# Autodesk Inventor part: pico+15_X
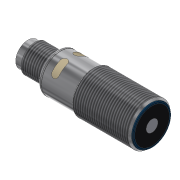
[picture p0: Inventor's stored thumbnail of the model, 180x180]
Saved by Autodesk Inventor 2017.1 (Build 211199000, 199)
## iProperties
Shininess: 20.0
Length Units: 11269
Angle Units: 11279
Time Units: 11290
Mass Units: 11283
Length Display Precision: 2
Angle Display Precision: 2
Part Number: pico+15_X
Material: Nichtrostender Stahl - 440C
Document SubType Name: Modellieren
Description: Ipc-25 /CXX/M18
Checked By: Alves
Created: 2005-08
Designer: Ohle
Manufacturer: Standard
Standards Organization: Custom
Appearance: Aluminium - poliert
Density: 0.0
Volumn: 0.0
Area: 0.0
PropertySet Name: Model Information
Control State: 0
Master: False
Checked Out: False
BESTELLNUMMER: Ipc-25 /CXX/M18
ME: ST
Title: Ipc Sensoren
Author: Ohle
Comments: keine Bemerkung
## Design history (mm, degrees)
sketch "Skizze10"
  geometry: L1 (-42.478, 0)-(2.095, 0); L2 (-38.478, 6.5)-(-38.478, 7.25); L3 (-45.9, 8)-(-45.9, 8); L4 (-22.728, 9)-(0.772, 9); L5 (2.085, 7.4)-(2.085, 2.5); L6 (2.085, 2.5)-(2.095, 2.5); L7 (2.095, 2.5)-(2.095, 0); L8 (2.095, 0)-(-82, 0); L9 (1.522, 8.25)-(1.522, 8.25); L10 (-23.478, 8.25)-(-22.728, 9); L11 (1.522, 8.25)-(0.772, 9); L12 (-49.978, 6)-(-38.978, 6); L13 (-36.878, 8.25)-(-23.478, 8.25); L14 (-50.478, 4.5)-(-42.478, 4.5); L15 (-42.478, 0)-(-42.478, 4.5); L16 (-36.978, 8.25)-(-37.478, 8.25); L17 (1.522, 8.25)-(1.522, 8.25); L18 (-38.978, 6)-(-38.478, 6.5); L19 (-50.478, 5.5)-(-50.478, 4.5); L20 (-50.478, 5.5)-(-49.978, 6); L21 (-36.978, 8.25)-(-36.978, 8.15); L22 (-36.978, 8.15)-(-36.878, 8.15); L23 (-36.878, 8.15)-(-36.878, 8.25); L24 (1.522, 8.25)-(1.595, 8.25); L25 (1.595, 8.25)-(1.795, 8.25); L26 (2.095, 7.95)-(2.095, 7.4); L27 (2.095, 7.4)-(2.085, 7.4); A1 r 1 centre (-37.478, 7.25) between (-37.478, 8.25) and (-38.478, 7.25); A2 r 0.3 centre (1.795, 7.95) between (2.095, 7.95) and (1.795, 8.25); 4 further points
  constraints: 54 end point, 8 point on line, 7 perpendicular, 5 parallel, 4 point on circle, 4 tangent, 2 centre point, 2 horizontal, 1 collinear
  dimensions: "d136" = 2.5 distance of L6.end L1.end; "d138" = 9 distance between parallel lines of L4 L8; "d171" = 4.5 distance between parallel lines of L14 L1; "d250" = 0.75 distance from line of L11.start L4; "d256" = 45 deg angle of L4 L10; "d257" = 8.25 distance between parallel lines of L8 L13; "d263" = 8.25 distance between parallel lines of L8 L16; "d266" = 12 distance from line of L2 L19.start; "d269" = 6 distance between parallel lines of L8 L12; "d289" = 135 deg angle of L11 L4; "d290" = 0.5 horizontal distance of L12.end L2.start; "d291" = 45 deg angle of L18 L12 (derived); "d293" = 0.5 horizontal distance of L19.start L12.start; "d294" = 45 deg angle of L20 L12 (derived); "d295" = 8 distance of L14.start L14.end; "d296" = 1.5 distance of L16.start point (-38.478, 8.25); "d297" = 0.1 distance of L21.end L22.end; "d298" = 8.15 distance between parallel lines of L22 L1; "d299" = 15 distance from line of L10.start L2; "d300" = 1 radius of A1; "d331" = 0.01 distance between parallel lines of L5 L7; "d334" = 0.5 distance of L24.end point (2.095, 8.25); "d335" = 0.3 radius of A2; "d337" = 25 distance of L10.start L11.start; "d338" = 0.01 distance between parallel lines of L26 L5; "d339" = 7.4 distance between parallel lines of L8 L27
revolve "Grundkörper pico+" sketch "Skizze10" stored, may be unused: angle "d168" = 90 deg
feature "Gewinde M12" dims "d174" = 10, "d175" = 0
feature "Gewinde M 18" dims "d179" = 10, "d180" = 0
workplane "Arbeitsebene1"
workplane "Arbeitsebene2"
sketch "Skizze13"
  geometry: L1 (-3.409, -3.409)-(3.61, 3.61); L2 (-3.439, 3.439)-(4.105, -4.105); L3 (-12.6, 0)-(12.6, 0) reference; C1 r 0.5 at (2.121, -2.121); C2 r 0.5 at (2.121, 2.121); C3 r 0.5 at (-2.121, 2.121); C4 r 0.5 at (-2.121, -2.121); C5 r 4.5 at (0, 0) reference; C6 r 0.5 at (0, 0); A1 r 3 centre (0, 0) between (-2.121, 2.121) and (2.121, 2.121); 2 further points
  constraints: 6 centre point, 6 point on line, 4 coincident, 4 end point, 4 equal radius, 4 point on circle, 1 horizontal alignment, 1 perpendicular
  dimensions: "d208" = 1 diameter of C3; "d209" = 6 diameter of A1
extrude "Pole" join sketch "Skizze13" distance "d212" = 7; taper "d213" = 0 deg
fillet "Rundung Pole" dims "d214" = 0.5
sketch "Skizze14"
  geometry: C1 r 0.5 at (0, -4.5); A1 r 4.5 centre (0, 0) between (4.435, -0.762) and (4.435, 0.762); A2 r 4.5 centre (0, 0) between (0, 4.5) and (0.499, 4.472) reference; A3 r 0.5 centre (0, 4.5) between (-0.499, 4.472) and (0.499, 4.472); 3 further points
  constraints: 9 point on circle, 3 centre point, 3 coincident, 1 horizontal alignment, 1 vertical alignment
  dimensions: "d215" = 9 diameter of A1; "d280" = 1 diameter of A3; "d330" = 1 diameter of C1
extrude "Verdrehsicherung" join sketch "Skizze14" distance "d217" = 7; taper "d218" = 0 deg
sketch "Skizze18"
  geometry: C1 r 7.25 at (0, 0) reference; C2 r 1 at (-8.15, 0)
  constraints: 1 centre point, 1 horizontal alignment
  dimensions: "d328" = 2 diameter of C2; "d329" = 8.15 distance of C1.centre C2.centre
extrude "Bohrung Ausrichtung" cut sketch "Skizze18" distance "d316" = 0.75; taper "d317" = 0 deg
workplane "Arbeitsebene4"
sketch "Skizze19"
  geometry: L1 (-38.478, 0)-(-30.18, 0); L2 (-34.178, -7.5)-(-34.178, -3); L3 (-31.178, -7.5)-(-31.178, -3); L4 (-31.178, 3)-(-31.178, 7.5); L5 (-34.178, 3)-(-34.178, 7.5); A1 r 1.5 centre (-32.678, 3) between (-31.178, 3) and (-34.178, 3); A2 r 1.5 centre (-32.678, -3) between (-34.178, -3) and (-31.178, -3); A3 r 1.5 centre (-32.678, 7.5) between (-31.178, 7.5) and (-34.178, 7.5); A4 r 1.5 centre (-32.678, -7.5) between (-34.178, -7.5) and (-31.178, -7.5); 4 further points; 1 other entity
  constraints: 10 end point, 8 point on circle, 8 tangent, 4 centre point, 3 equal radius, 2 vertical alignment, 1 horizontal, 2 other
  dimensions: "d319" = 3 diameter of A2; "d320" = 6 distance of A2.centre A1.centre; "d321" = 4.5 distance of A1.centre A3.centre; "d322" = 4.5 distance of A4.centre A2.centre; "d323" = 3 distance from line of A2.centre L1; "d324" = 5.8 dimension on A1.centre; "d325" = 5.8 dimension on A2.centre
feature "Prägen LED-Fenster" sketch "Skizze19" dims "d326" = 0.01, "d327" = 0
sketch "Skizze20"
  geometry: C1 r 5.5 at (0, 0) reference; C2 r 4.5 at (0, 0) reference; C3 r 4.15 at (0, 0); C4 r 5.25 at (0, 0); 1 further point
  constraints: 2 centre point
  dimensions: "d340" = 8.3 diameter of C3; "d341" = 10.5 diameter of C4
extrude "Extrusion5" join sketch "Skizze20" stored distance "d342" = 1; taper "d343" = 0 deg
sketch "Skizze21"
  geometry: C1 r 4.15 at (0, 0) reference; C2 r 5.25 at (0, 0) reference; C3 r 6 at (0, 0); 1 further point
  constraints: 1 centre point
  dimensions: "d344" = 12 diameter of C3
extrude "Extrusion6" cut sketch "Skizze21" distance "d345" = 2.6; taper "d346" = 0 deg
chamfer "Fase2" distance "d347" = 0.75; stored, may be unused: second distance "d348" = 2, angle "d349" = 30 deg
node "Volumenkörper1"
node "Volumenkörper"
node "Flächenkörper"
node "Projizierte Kontur2"
node "Projizierte Kontur3"
other parameters: "d10" = 14, "d73" = -35, "d130" = 0.2, "d207" = -95.5, "d318" = 8.25
